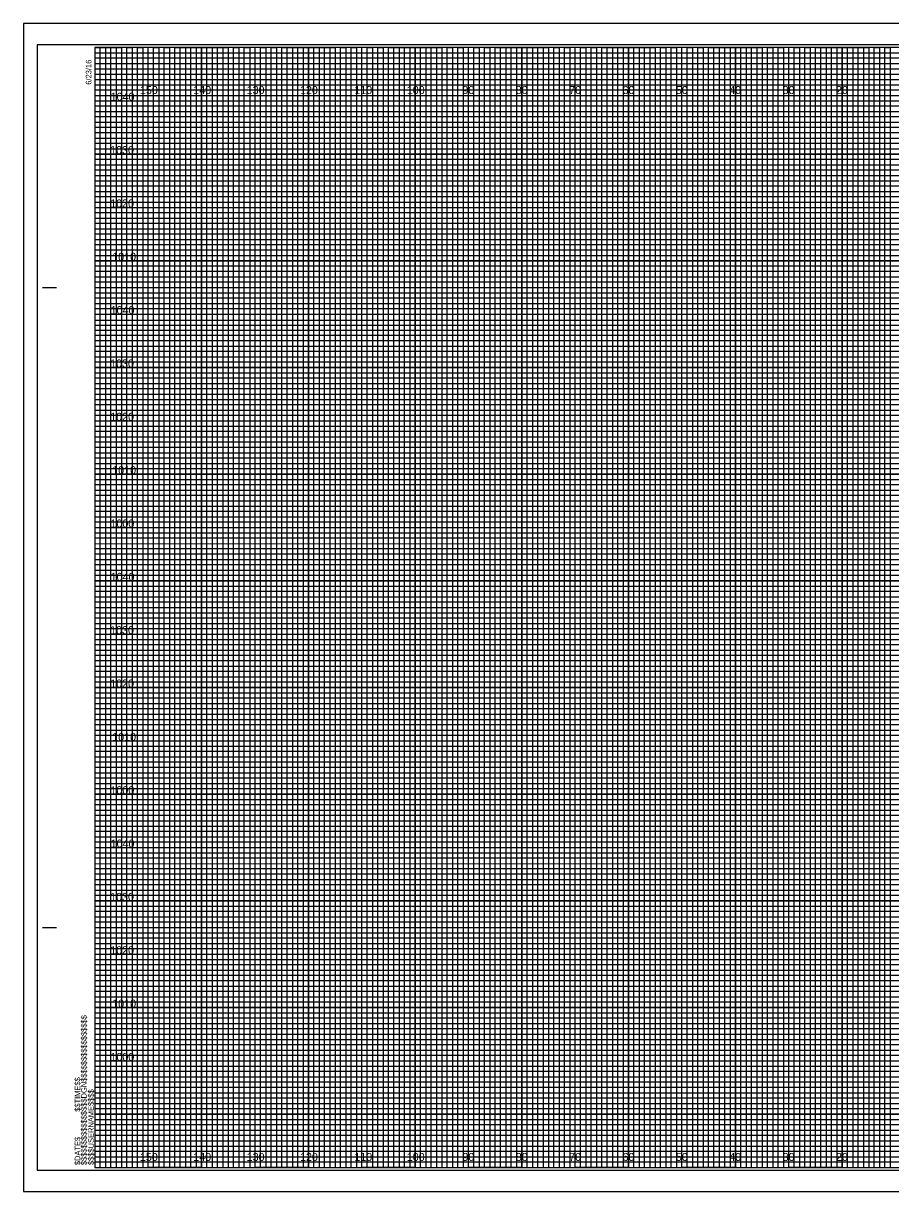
# Model space of a CAD drawing. Extents: x -13 to 323, y 5276 to 5494.
# Drawn here: x -13.4 to 149.1, y 5275.5 to 5494.5 of the extents above; entities that cross this region are included whole.
import ezdxf

# ---------------------------------------------------------------- set-up
doc = ezdxf.new("R2010")
doc.units = 0
for name, color, linetype in [('Prop XS Elevation Labels', 7, 'Continuous'), ('Prop XS Offset Labels', 7, 'Continuous'), ('Sheet Block System Information CELL', 7, 'Continuous'), ('Sheet Cross Section CELL', 7, 'Continuous'), ('Sheet Cross Section Grid Major CELL', 7, 'Continuous'), ('Sheet Cross Section Grid Middle CELL', 7, 'Continuous'), ('Sheet Cross Section Grid Minor 1 CELL', 7, 'Continuous'), ('Sheet Cross Section Grid Minor 2 CELL', 7, 'Continuous'), ('Sheet Cutting Line CELL', 7, 'Continuous'), ('Sheet DOT Grid CELL', 7, 'Continuous'), ('Sheet Plot Border Inside CELL', 7, 'Continuous'), ('Sheet Plot Border Outside CELL', 7, 'Continuous')]:
    doc.layers.add(name, color=color, linetype=linetype)

msp = doc.modelspace()

# ---------------------------------------------------------------- linework, layer by layer
at = {"layer": 'Sheet Block System Information CELL'}
msp.add_line((0, 5280), (0, 5280), dxfattribs=at)
msp.add_line((0, 5280), (0, 5280), dxfattribs=at)
at = {"layer": 'Sheet Cross Section CELL'}
for p, q in [((-9.8, 5445), (-7.3, 5445)), ((-9.7, 5445), (-7.2, 5445)), ((-9.8, 5325), (-7.3, 5325)), ((-9.7, 5325), (-7.2, 5325)), ((0, 5280), (0, 5280)), ((0, 5280), (0, 5280)), ((0, 5280), (0, 5280)), ((0, 5280), (0, 5280)), ((0, 5280), (0, 5280)), ((0, 5280), (0, 5280)), ((0, 5280), (0, 5280))]:
    msp.add_line(p, q, dxfattribs=at)
msp.add_lwpolyline([(320, 5490), (0, 5490), (0, 5280), (320, 5280)], close=True, dxfattribs=at)
at = {"layer": 'Sheet Cross Section Grid Major CELL'}
for p, q in [((10, 5490), (0, 5490)), ((10, 5280), (10, 5490)), ((30, 5490), (20, 5490)), ((20, 5490), (20, 5280)), ((30, 5280), (30, 5490)), ((50, 5490), (40, 5490)), ((40, 5490), (40, 5280)), ((50, 5280), (50, 5490)), ((70, 5490), (60, 5490)), ((60, 5490), (60, 5280)), ((70, 5280), (70, 5490)), ((90, 5490), (80, 5490)), ((80, 5490), (80, 5280)), ((90, 5280), (90, 5490)), ((110, 5490), (100, 5490)), ((100, 5490), (100, 5280)), ((110, 5280), (110, 5490)), ((130, 5490), (120, 5490)), ((120, 5490), (120, 5280)), ((130, 5280), (130, 5490)), ((150, 5490), (140, 5490)), ((140, 5490), (140, 5280)), ((20, 5280), (10, 5280)), ((40, 5280), (30, 5280)), ((60, 5280), (50, 5280)), ((80, 5280), (70, 5280)), ((100, 5280), (90, 5280)), ((120, 5280), (110, 5280)), ((140, 5280), (130, 5280))]:
    msp.add_line(p, q, dxfattribs=at)
for points in [[(0, 5480), (320, 5480), (320, 5470), (0, 5470)], [(0, 5460), (320, 5460), (320, 5450), (0, 5450)], [(0, 5440), (320, 5440), (320, 5430), (0, 5430)], [(0, 5420), (320, 5420), (320, 5410), (0, 5410)], [(0, 5400), (320, 5400), (320, 5390), (0, 5390)], [(0, 5380), (320, 5380), (320, 5370), (0, 5370)], [(0, 5360), (320, 5360), (320, 5350), (0, 5350)], [(0, 5340), (320, 5340), (320, 5330), (0, 5330)], [(0, 5320), (320, 5320), (320, 5310), (0, 5310)], [(0, 5300), (320, 5300), (320, 5290), (0, 5290)]]:
    msp.add_lwpolyline(points, dxfattribs=at)
at = {"layer": 'Sheet Cross Section Grid Middle CELL'}
for points in [[(0, 5490), (5, 5490), (5, 5280), (15, 5280), (15, 5490), (25, 5490), (25, 5280), (35, 5280), (35, 5490), (45, 5490), (45, 5280), (55, 5280), (55, 5490), (65, 5490), (65, 5280), (75, 5280), (75, 5490), (85, 5490), (85, 5280), (95, 5280), (95, 5490), (105, 5490), (105, 5280), (115, 5280), (115, 5490), (125, 5490), (125, 5280), (135, 5280), (135, 5490), (145, 5490), (145, 5280), (155, 5280)], [(0, 5485), (275, 5485)], [(0, 5465), (320, 5465), (320, 5475), (0, 5475)], [(0, 5445), (320, 5445), (320, 5455), (0, 5455)], [(0, 5425), (320, 5425), (320, 5435), (0, 5435)], [(0, 5405), (320, 5405), (320, 5415), (0, 5415)], [(0, 5385), (320, 5385), (320, 5395), (0, 5395)], [(0, 5365), (320, 5365), (320, 5375), (0, 5375)], [(0, 5345), (320, 5345), (320, 5355), (0, 5355)], [(0, 5325), (320, 5325), (320, 5335), (0, 5335)], [(0, 5305), (320, 5305), (320, 5315), (0, 5315)], [(0, 5285), (320, 5285), (320, 5295), (0, 5295)]]:
    msp.add_lwpolyline(points, dxfattribs=at)
at = {"layer": 'Sheet Cross Section Grid Minor 1 CELL'}
for p, q in [((0, 5489), (260, 5489)), ((260, 5487.98), (0, 5487.98)), ((0, 5487.98), (0, 5487)), ((0, 5487), (260, 5487)), ((260, 5485.89), (0, 5485.89)), ((0, 5485.89), (0, 5484)), ((0, 5484), (320, 5484))]:
    msp.add_line(p, q, dxfattribs=at)
for points in [[(0, 5483), (270, 5483), (320, 5483), (320, 5482), (0, 5482)], [(0, 5481), (320, 5481), (320, 5479), (0, 5479)], [(0, 5478), (320, 5478), (320, 5477), (0, 5476.98)], [(0, 5476), (320, 5476), (320, 5474), (0, 5474)], [(0, 5473), (320, 5473), (320, 5472), (0, 5472)], [(0, 5471), (320, 5471), (320, 5469), (0, 5469)], [(0, 5468), (320, 5468), (320, 5467), (0, 5467)], [(0, 5466), (320, 5466), (320, 5464), (0, 5464)], [(0, 5463), (320, 5463), (320, 5462), (0, 5462)], [(0, 5461), (320, 5461), (320, 5459), (0, 5459)], [(0, 5458), (320, 5458), (320, 5457), (0, 5457)], [(0, 5456), (320, 5456), (320, 5453.95), (320, 5453), (320, 5452), (0, 5452)], [(0, 5454), (320, 5454), (320, 5453), (0, 5453)], [(0, 5451), (320, 5451), (320, 5449), (0, 5449.03)], [(0, 5449.03), (320, 5449), (320, 5448), (0, 5448)], [(0, 5447), (320, 5447), (320, 5446), (0, 5446)], [(0, 5444), (320, 5444), (320, 5443), (0, 5443)], [(0, 5442), (320, 5442), (320, 5441), (0, 5441)], [(-0.07, 5438.89), (320, 5438.89), (320, 5437.88), (-0.07, 5437.88)], [(0, 5437), (320, 5437), (320, 5436), (0, 5436)], [(0, 5434), (320, 5434), (320, 5433), (0, 5433)], [(0, 5432), (320, 5432), (320, 5431), (0, 5431)], [(0, 5429), (320, 5429), (320, 5428), (0, 5428)], [(0, 5427), (320, 5427), (320, 5426), (0, 5426)], [(0, 5424), (320, 5424), (320, 5423), (0, 5423)], [(0, 5422), (320, 5422), (320, 5421), (0, 5421)], [(0, 5419), (320, 5419), (319.99, 5417.98), (0, 5418)], [(0, 5417), (320, 5417), (320, 5416), (0, 5416)], [(0, 5414), (320, 5414), (320, 5413), (0, 5413)], [(0, 5412), (320, 5412), (320, 5411), (0, 5411)], [(0, 5409), (320, 5409), (320, 5408), (0, 5408)], [(0, 5407), (320, 5407), (320, 5406), (0, 5406)], [(0, 5404), (320, 5404), (320, 5403), (0, 5403)], [(0, 5402), (320, 5402), (320, 5401), (0, 5401)], [(0, 5399), (320, 5399), (320, 5398), (0, 5398)], [(0, 5396.99), (320.07, 5396.91), (320, 5396), (0, 5396)], [(0, 5394), (320, 5394), (320, 5393), (0, 5393)], [(0, 5392), (320, 5392), (320, 5391), (0, 5391)], [(0, 5389), (320, 5389), (320, 5388), (0, 5388)], [(0, 5387), (320, 5387), (320, 5386), (0, 5386)], [(0, 5384), (320, 5384), (320, 5383), (0, 5383)], [(0, 5382), (320, 5382), (320, 5381), (0, 5381)], [(0, 5379), (320, 5379), (320, 5378), (0, 5378)], [(0, 5377), (320, 5377), (320, 5376), (0, 5376)], [(0, 5374), (320, 5374), (320, 5373), (0, 5373)], [(0, 5372), (320, 5372), (320, 5371), (0, 5371)], [(0, 5369), (320, 5369), (320, 5368), (0, 5368)], [(0, 5367), (320, 5367), (320, 5366), (0, 5366)], [(0, 5364), (320, 5364), (320, 5363), (0, 5363)], [(0, 5362), (320, 5362), (320, 5361), (0, 5361)], [(0, 5359), (320, 5359), (319.99, 5357.98), (0, 5358)], [(0, 5357), (320, 5357), (320, 5356), (0, 5356)], [(0, 5354), (320, 5354), (320, 5353), (0, 5353)], [(0, 5352), (320, 5352), (320, 5351), (0, 5351)], [(0, 5349), (320, 5349), (320, 5348), (0, 5348)], [(0, 5347), (320, 5347), (320, 5346), (0, 5346)], [(0, 5344), (320, 5344), (320, 5343), (0, 5343)], [(0, 5342), (320, 5342), (320, 5341), (0, 5341)], [(0, 5339), (320, 5339), (320, 5338), (0, 5338)], [(0, 5336.99), (320.07, 5336.91), (320, 5336), (0, 5336)], [(0, 5334), (320, 5334), (320, 5333), (0, 5333)], [(0, 5332), (320, 5332), (320, 5331), (0, 5331)], [(0, 5329), (320, 5329), (320, 5328), (0, 5328)], [(0, 5327), (320, 5327), (320, 5326), (0, 5326)], [(0, 5324), (320, 5324), (320, 5323), (0, 5323)], [(0, 5322), (320, 5322), (320, 5321), (0, 5321)], [(0, 5319), (320, 5319), (320, 5318), (0, 5318)], [(0, 5317), (320, 5317), (320, 5316), (0, 5316)], [(0, 5314), (320, 5314), (320, 5313), (0, 5313)], [(0, 5312), (320, 5312), (320, 5311), (0, 5311)], [(0, 5309), (320, 5309), (320, 5308), (0, 5308)], [(0, 5307), (320, 5307), (320, 5306), (0, 5306)], [(0, 5304), (320, 5304), (320, 5303), (0, 5303)], [(0, 5302), (320, 5302), (320, 5301), (0, 5301)], [(0, 5299), (320, 5299), (320, 5298), (0, 5298)], [(0, 5297), (320, 5297), (320, 5296), (0, 5296)], [(0, 5294), (320, 5294), (320, 5293), (0, 5293)], [(0, 5292), (320, 5292), (320, 5291), (0, 5291)], [(0, 5289), (320, 5289), (320, 5288), (0, 5288)], [(0, 5287), (320, 5287), (320, 5286), (0, 5286)], [(0, 5284), (320, 5284), (320, 5283), (0, 5283)], [(0, 5282), (320, 5282), (320, 5281), (0, 5281)]]:
    msp.add_lwpolyline(points, dxfattribs=at)
at = {"layer": 'Sheet Cross Section Grid Minor 2 CELL'}
for points in [[(0, 5280), (1, 5280), (1, 5490), (2, 5490), (2, 5280)], [(2, 5280), (3, 5280), (3, 5490), (4, 5490), (4, 5280)], [(5, 5280), (6, 5280), (6, 5490), (7, 5490), (7, 5280)], [(7, 5280), (8, 5280), (8, 5490), (9, 5490), (9, 5280)], [(10, 5280), (11, 5280), (11, 5490), (12, 5490), (12, 5280)], [(12, 5280), (13, 5280), (13, 5490), (14, 5490), (14, 5280)], [(15, 5280), (16, 5280), (16, 5490), (17, 5490), (17, 5280)], [(17, 5280), (18, 5280), (18, 5490), (19, 5490), (19, 5280)], [(20, 5280), (21, 5280), (21, 5490), (22, 5490), (22, 5280)], [(22, 5280), (23, 5280), (23, 5490), (24, 5490), (24, 5280)], [(25, 5280), (26, 5280), (26, 5490), (27, 5490), (27, 5280)], [(27, 5280), (28, 5280), (28, 5490), (29, 5490), (29, 5280)], [(30, 5280), (31, 5280), (31, 5490), (32, 5490), (32, 5280)], [(32, 5280), (33, 5280), (33, 5490), (34, 5490), (34, 5280)], [(35, 5280), (36, 5280), (36, 5490), (37, 5490), (37, 5280)], [(37, 5280), (38, 5280), (38, 5490), (39, 5490), (39, 5280)], [(40, 5280), (41, 5280), (41, 5490), (42, 5490), (42, 5280)], [(42, 5280), (43, 5280), (43, 5490), (44, 5490), (44, 5280)], [(45, 5280), (46, 5280), (46, 5490), (47, 5490), (47, 5280)], [(47, 5280), (48, 5280), (48, 5490), (49, 5490), (49, 5280)], [(50, 5280), (51, 5280), (51, 5490), (52, 5490), (52, 5280)], [(52, 5280), (53, 5280), (53, 5490), (54, 5490), (54, 5280)], [(55, 5280), (56, 5280), (56, 5490), (57, 5490), (57, 5280)], [(57, 5280), (58, 5280), (58, 5490), (59, 5490), (59, 5280)], [(60, 5280), (61, 5280), (61, 5490), (62, 5490), (62, 5280)], [(62, 5280), (63, 5280), (63, 5490), (64, 5490), (64, 5280)], [(65, 5280), (66, 5280), (66, 5490), (67, 5490), (67, 5280)], [(67, 5280), (68, 5280), (68, 5490), (69, 5490), (69, 5280)], [(70, 5280), (71, 5280), (71, 5490), (72, 5490), (72, 5280)], [(72, 5280), (73, 5280), (73, 5490), (74, 5490), (74, 5280)], [(75, 5280), (76, 5280), (76, 5490), (77, 5490), (77, 5280)], [(77, 5280), (78, 5280), (78, 5490), (79, 5490), (79, 5280)], [(80, 5280), (81, 5280), (81, 5490), (82, 5490), (82, 5280)], [(82, 5280), (83, 5280), (83, 5490), (84, 5490), (84, 5280)], [(85, 5280), (86, 5280), (86, 5490), (87, 5490), (87, 5280)], [(87, 5280), (88, 5280), (88, 5490), (89, 5490), (89, 5280)], [(90, 5280), (91, 5280), (91, 5490), (92, 5490), (92, 5280)], [(92, 5280), (93, 5280), (93, 5490), (94, 5490), (94, 5280)], [(95, 5280), (96, 5280), (96, 5490), (97, 5490), (97, 5280)], [(97, 5280), (98, 5280), (98, 5490), (99, 5490), (99, 5280)], [(100, 5280), (101, 5280), (101, 5490), (102, 5490), (102, 5280)], [(102, 5280), (103, 5280), (103, 5490), (104, 5490), (104, 5280)], [(105, 5280), (106, 5280), (106, 5490), (107, 5490), (107, 5280)], [(107, 5280), (108, 5280), (108, 5490), (109, 5490), (109, 5280)], [(110, 5280), (111, 5280), (111, 5490), (112, 5490), (112, 5280)], [(112, 5280), (113, 5280), (113, 5490), (114, 5490), (114, 5280)], [(115, 5280), (116, 5280), (116, 5490), (117, 5490), (117, 5280)], [(117, 5280), (118, 5280), (118, 5490), (119, 5490), (119, 5280)], [(120, 5280), (121, 5280), (121, 5490), (122, 5490), (122, 5280)], [(122, 5280), (123, 5280), (123, 5490), (124, 5490), (124, 5280)], [(125, 5280), (126, 5280), (126, 5490), (127, 5490), (127, 5280)], [(127, 5280), (128, 5280), (128, 5490), (129, 5490), (129, 5280)], [(130, 5280), (131, 5280), (131, 5490), (132, 5490), (132, 5280)], [(132, 5280), (133, 5280), (133, 5490), (134, 5490), (134, 5280)], [(135, 5280), (136, 5280), (136, 5490), (137, 5490), (137, 5280)], [(137, 5280), (138, 5280), (138, 5490), (139, 5490), (139, 5280)], [(140, 5280), (141, 5280), (141, 5490), (142, 5490), (142, 5280)], [(142, 5280), (143, 5280), (143, 5490), (144, 5490), (144, 5280)], [(145, 5280), (146, 5280), (146, 5490), (147, 5490), (147, 5280)], [(147, 5280), (148, 5280), (148, 5490), (149, 5490), (149, 5280)]]:
    msp.add_lwpolyline(points, dxfattribs=at)
at = {"layer": 'Sheet Cutting Line CELL'}
for p, q in [((323.3, 5494.5), (-13.4, 5494.5)), ((-13.4, 5494.5), (-13.4, 5275.5)), ((-13.4, 5275.5), (323.3, 5275.5))]:
    msp.add_line(p, q, dxfattribs=at)
at = {"layer": 'Sheet DOT Grid CELL'}
for p, q in [((10, 5280), (10, 5490)), ((20, 5280), (20, 5490)), ((30, 5280), (30, 5490)), ((40, 5280), (40, 5490)), ((50, 5280), (50, 5490)), ((60, 5280), (60, 5490)), ((70, 5280), (70, 5490)), ((80, 5280), (80, 5490)), ((90, 5280), (90, 5490)), ((100, 5280), (100, 5490)), ((110, 5280), (110, 5490)), ((120, 5280), (120, 5490)), ((130, 5280), (130, 5490)), ((140, 5280), (140, 5490)), ((0, 5480), (320, 5480)), ((0, 5470), (320, 5470)), ((0, 5460), (320, 5460)), ((0, 5450), (320, 5450)), ((0, 5440), (320, 5440)), ((0, 5430), (320, 5430)), ((0, 5420), (320, 5420)), ((0, 5410), (320, 5410)), ((0, 5400), (320, 5400)), ((0, 5390), (320, 5390)), ((0, 5380), (320, 5380)), ((0, 5370), (320, 5370)), ((0, 5360), (320, 5360)), ((0, 5350), (320, 5350)), ((0, 5340), (320, 5340)), ((0, 5330), (320, 5330)), ((0, 5320), (320, 5320)), ((0, 5310), (320, 5310)), ((0, 5300), (320, 5300)), ((0, 5290), (320, 5290))]:
    msp.add_line(p, q, dxfattribs=at)
at = {"layer": 'Sheet Plot Border Inside CELL'}
msp.add_lwpolyline([(-10.8, 5279.5), (322.4, 5279.5), (322.4, 5490.5), (-10.8, 5490.5)], close=True, dxfattribs=at)
at = {"layer": 'Sheet Plot Border Outside CELL'}
msp.add_lwpolyline([(-13.4, 5275.5), (323.3, 5275.5), (323.3, 5494.5), (-13.4, 5494.5)], close=True, dxfattribs=at)

# ---------------------------------------------------------------- texts
at = {"layer": 'Prop XS Elevation Labels'}
for s, p in [('1040', (2.95, 5480)), ('1030', (2.86, 5470)), ('1020', (2.87, 5460)), ('1010', (3.25, 5450)), ('1040', (2.95, 5440)), ('1030', (2.86, 5430)), ('1020', (2.87, 5420)), ('1010', (3.25, 5410)), ('1000', (2.92, 5400)), ('1040', (2.95, 5390)), ('1030', (2.86, 5380)), ('1020', (2.87, 5370)), ('1010', (3.25, 5360)), ('1000', (2.92, 5350)), ('1040', (2.95, 5340)), ('1030', (2.86, 5330)), ('1020', (2.87, 5320)), ('1010', (3.25, 5310)), ('1000', (2.92, 5300))]:
    msp.add_text(s, height=1.5, dxfattribs=at).set_placement(p)
at = {"layer": 'Prop XS Offset Labels'}
for s, p in [('150', (8.44, 5481.25)), ('140', (18.44, 5481.25)), ('130', (28.44, 5481.25)), ('120', (38.44, 5481.25)), ('110', (48.62, 5481.25)), ('100', (58.44, 5481.25)), ('90', (68.86, 5481.25)), ('80', (78.86, 5481.25)), ('70', (88.86, 5481.25)), ('60', (98.86, 5481.25)), ('50', (108.86, 5481.25)), ('40', (118.86, 5481.25)), ('30', (128.86, 5481.25)), ('20', (138.86, 5481.25)), ('150', (8.44, 5281.25)), ('140', (18.44, 5281.25)), ('130', (28.44, 5281.25)), ('120', (38.44, 5281.25)), ('110', (48.62, 5281.25)), ('100', (58.44, 5281.25)), ('90', (68.86, 5281.25)), ('80', (78.86, 5281.25)), ('70', (88.86, 5281.25)), ('60', (98.86, 5281.25)), ('50', (108.86, 5281.25)), ('40', (118.86, 5281.25)), ('30', (128.86, 5281.25)), ('20', (138.86, 5281.25))]:
    msp.add_text(s, height=1.5, dxfattribs=at).set_placement(p)
at = {"layer": 'Sheet Block System Information CELL'}
for s, p in [('$$$$$$$$$$$$$$$$DGN$$$$$$$$$$$$$$$$', (-1.53, 5280.47)), ('$$TIME$$', (-2.74, 5290.47)), ('$$$$USERNAME$$$$', (-0.21, 5280.48)), ('$DATE$', (-2.74, 5280.47))]:
    msp.add_text(s, height=1.05, rotation=90, dxfattribs=at).set_placement(p)
at = {"layer": 'Sheet Cross Section CELL'}
msp.add_text('6/23/16', height=1.05, rotation=90, dxfattribs=at).set_placement((-0.65, 5483))

doc.saveas('drawing.dxf')
